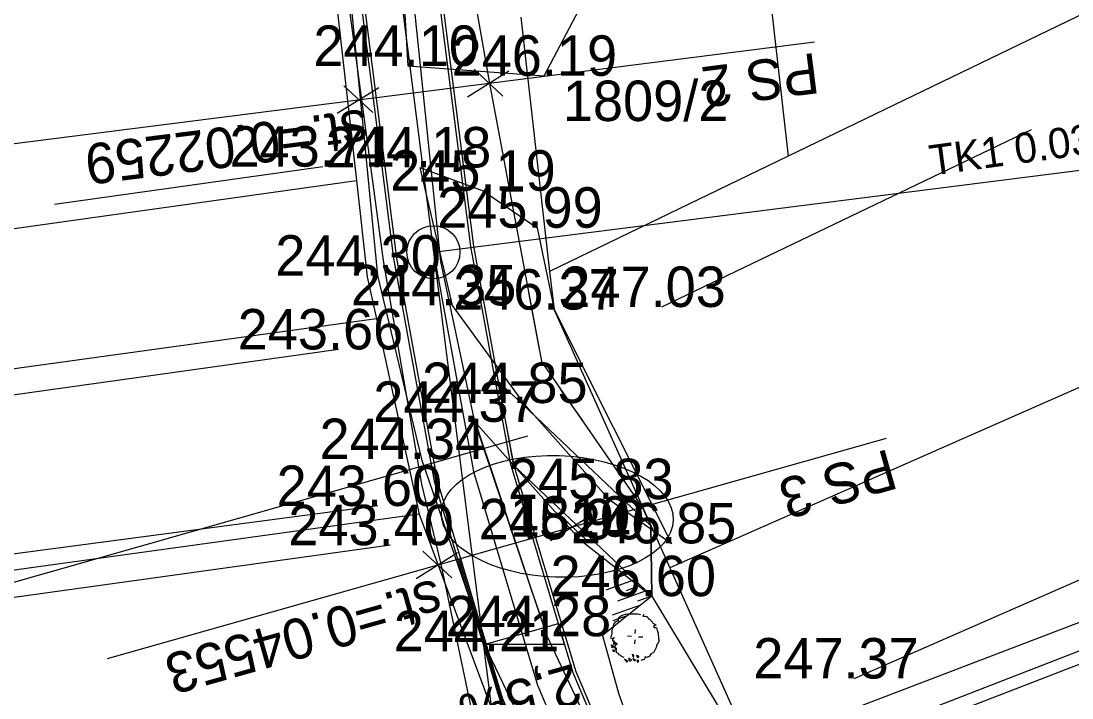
# Model space of a CAD drawing. Extents: x -601754 to -601440, y -1201912 to -1200862.
# Drawn here: x -601652.4 to -601600.5, y -1200940.1 to -1200906.7 of the extents above; entities that cross this region are included whole.
import ezdxf

# ---------------------------------------------------------------- set-up
doc = ezdxf.new("R2010")
doc.units = 0
for name, color, linetype in [('Hranice parcel', 7, 'Continuous'), ('Parcelní čísla', 7, 'Continuous'), ('u_dotčené parcely', 7, 'Continuous'), ('u_drén', 7, 'Continuous'), ('u_hrany', 7, 'Continuous'), ('u_krizky', 7, 'Continuous'), ('u_návrh', 7, 'Continuous'), ('u_oblouky', 7, 'Continuous'), ('u_osa', 7, 'Continuous'), ('u_popis', 7, 'Continuous'), ('u_popis oblouky', 7, 'Continuous'), ('u_pricne_cesta', 7, 'Continuous'), ('u_rozšíření v obloucích', 7, 'Continuous'), ('u_sklony', 7, 'Continuous'), ('u_terénní úpravy', 7, 'Continuous'), ('u_vysadba_SO_101', 7, 'Continuous'), ('u_vyska', 7, 'Continuous')]:
    doc.layers.add(name, color=color, linetype=linetype)

msp = doc.modelspace()

# ---------------------------------------------------------------- linework, layer by layer
at = {"layer": 'Hranice parcel'}
for p, q in [((-601637.83, -1200896.61), (-601635.81, -1200914.55)), ((-601615.91, -1200900.68), (-601614.48, -1200913.35)), ((-601627.69, -1200906.47), (-601626.27, -1200919.05)), ((-601614.48, -1200913.35), (-601626.27, -1200919.05)), ((-601751.585, -1200930.722), (-601635.81, -1200914.55)), ((-601634.83, -1200921.38), (-601751.585, -1200937.583)), ((-601634.83, -1200921.38), (-601632.72, -1200931.05)), ((-601632.72, -1200931.05), (-601751.585, -1200947.48)), ((-601632.72, -1200931.05), (-601626.75, -1200947.04)), ((-601620.33, -1200933.7), (-601616.34, -1200942.61))]:
    msp.add_line(p, q, dxfattribs=at)
for points in [[(-601480.72, -1200862.73), (-601552.37, -1200903.73), (-601620.33, -1200933.7)], [(-601514.155, -1200862.355), (-601515.21, -1200862.87), (-601539.23, -1200875.18), (-601559.8, -1200886.93), (-601614.48, -1200913.35)], [(-601474.14, -1200873.18), (-601548.57, -1200915.94), (-601568.93, -1200924.49), (-601616.34, -1200942.61)], [(-601472.81, -1200874.75), (-601548.9, -1200918.67), (-601615.4, -1200944.4)], [(-601611.28, -1200963.08), (-601614.07, -1200959.31), (-601621.9, -1200946.57), (-601626.39, -1200937.08), (-601630.02, -1200926.25), (-601631.65, -1200918.55), (-601633.57, -1200899.96), (-601633.33, -1200887.98), (-601632.07, -1200885.6), (-601629.11, -1200882.26)], [(-601635.81, -1200914.55), (-601635.28, -1200919.31), (-601634.83, -1200921.38)], [(-601626.27, -1200919.05), (-601626.05, -1200920.94), (-601620.33, -1200933.7)]]:
    msp.add_lwpolyline(points, dxfattribs=at)
at = {"layer": 'u_dotčené parcely'}
msp.add_ellipse((-601625.886, -1200931.156), major_axis=(-5.729, 0.182), ratio=0.524694, dxfattribs=at)
at = {"layer": 'u_drén'}
msp.add_lwpolyline([(-601630.738, -1200933.27), (-601628.676, -1200940.153), (-601624.291, -1200950.498), (-601618.798, -1200960.3), (-601612.295, -1200969.398), (-601587.744, -1201000.039)], dxfattribs=at)
at = {"layer": 'u_hrany'}
for points in [[(-601637.65, -1200892.44), (-601636.56, -1200901.01), (-601634.78, -1200919.25), (-601632.6, -1200928.32), (-601629.33, -1200937.82), (-601624.51, -1200947.91), (-601616.86, -1200961.13), (-601606.97, -1200974.25), (-601596.82, -1200985.88), (-601582.46, -1201002.22), (-601574.49, -1201012.64), (-601569.33, -1201022.81), (-601566.79, -1201038.25), (-601566.21, -1201048.21)], [(-601634.24, -1200892.15), (-601633.27, -1200908.88), (-601626.53, -1200909.37)], [(-601626.53, -1200909.37), (-601624.49, -1200905.48)], [(-601620.72, -1200920.8), (-601602.45, -1200912.02)], [(-601650.73, -1200915.71), (-601637.47, -1200913.86)], [(-601632.69, -1200913.9), (-601629.56, -1200915.05), (-601626.89, -1200916.88)], [(-601632.69, -1200913.9), (-601631.08, -1200920.72), (-601627.56, -1200925.55), (-601623.34, -1200930.3), (-601620.24, -1200932.49)], [(-601626.89, -1200916.88), (-601626.05, -1200920.93), (-601620.24, -1200932.49)], [(-601636.71, -1200922.9), (-601654.69, -1200925.42)], [(-601629.97, -1200926.48), (-601624.78, -1200932.29), (-601621.22, -1200935.1)], [(-601568.57, -1201015.08), (-601571.45, -1201010.54), (-601577.11, -1201003.42), (-601594.37, -1200984.29), (-601604.5, -1200972.6), (-601614.07, -1200959.31), (-601621.9, -1200946.57), (-601626.39, -1200937.08), (-601629.97, -1200926.48)], [(-601634.75, -1200930.64), (-601653.18, -1200933.08)], [(-601611.21, -1200939.17), (-601592.25, -1200930.86)], [(-601634.14, -1200932.58), (-601652.73, -1200935.16)], [(-601611.85, -1200942.37), (-601592.5, -1200934.86)], [(-601621.22, -1200935.1), (-601608.09, -1200956.91)], [(-601629.33, -1200937.82), (-601626.28, -1200948.41), (-601618.2, -1200962.23), (-601609.12, -1200975.86), (-601600.84, -1200990.01)]]:
    msp.add_lwpolyline(points, dxfattribs=at)
at = {"layer": 'u_krizky'}
for p, q in [((-601628.572, -1200910.369), (-601629.998, -1200909.049)), ((-601628.279, -1200909.142), (-601630.331, -1200910.422)), ((-601634.715, -1200909.96), (-601636.768, -1200911.24)), ((-601635.009, -1200911.186), (-601636.435, -1200909.867)), ((-601624.166, -1200931.081), (-601626.218, -1200932.36)), ((-601624.459, -1200932.307), (-601625.885, -1200930.987)), ((-601630.814, -1200932.962), (-601632.867, -1200934.242)), ((-601631.107, -1200934.188), (-601632.534, -1200932.869))]:
    msp.add_line(p, q, dxfattribs=at)
at = {"layer": 'u_návrh'}
for p, q in [((-601621.265, -1200931.615), (-601628.812, -1200924.471)), ((-601621.22, -1200935.1), (-601628.022, -1200928.661)), ((-601621.22, -1200935.1), (-601621.265, -1200931.615))]:
    msp.add_line(p, q, dxfattribs=at)
for points in [[(-601634.025, -1200887.577), (-601630.185, -1200917.812), (-601628.225, -1200928.505), (-601625.119, -1200938.871), (-601620.896, -1200948.834), (-601615.607, -1200958.274), (-601609.285, -1200967.119), (-601584.73, -1200997.764)], [(-601633.876, -1200887.558), (-601630.036, -1200917.789), (-601628.079, -1200928.47), (-601624.978, -1200938.82), (-601620.761, -1200948.768), (-601615.48, -1200958.194), (-601609.165, -1200967.028), (-601578.723, -1201005.021)], [(-601637.844, -1200888.062), (-601633.991, -1200918.402), (-601631.974, -1200929.408), (-601628.747, -1200940.179), (-601624.358, -1200950.531), (-601618.862, -1200960.341), (-601612.355, -1200969.444), (-601581.832, -1201007.537)], [(-601637.695, -1200888.043), (-601633.842, -1200918.379), (-601631.828, -1200929.372), (-601628.605, -1200940.128), (-601624.223, -1200950.465), (-601618.735, -1200960.26), (-601612.236, -1200969.353), (-601587.617, -1201000.078)], [(-601621.265, -1200931.615), (-601621.673, -1200930.705), (-601626.671, -1200923.479)]]:
    msp.add_lwpolyline(points, dxfattribs=at)
at = {"layer": 'u_oblouky'}
for q in [(-601592.583, -1200913.087), (-601628.449, -1200946.159)]:
    msp.add_line((-601632.013, -1200918.095), q, dxfattribs=at)
msp.add_circle((-601632.013, -1200918.095), 1.311, dxfattribs=at)
at = {"layer": 'u_osa'}
msp.add_lwpolyline([(-601635.86, -1200887.81), (-601632.013, -1200918.095), (-601630.026, -1200928.939), (-601626.862, -1200939.5), (-601622.56, -1200949.65), (-601617.171, -1200959.267), (-601610.76, -1200968.236), (-601578.672, -1201008.284), (-601575.031, -1201013.469), (-601572.075, -1201019.074), (-601569.852, -1201025.007), (-601568.398, -1201031.174), (-601566.15, -1201044.408), (-601565.576, -1201049.148), (-601565.456, -1201053.922), (-601565.793, -1201058.685), (-601566.228, -1201062.343), (-601567.198, -1201067.854), (-601568.778, -1201073.221), (-601570.948, -1201078.378), (-601573.681, -1201083.261), (-601575.226, -1201085.692), (-601578.132, -1201090.011)], dxfattribs=at)
at = {"layer": 'u_popis'}
msp.add_line((-601660.34, -1200936.567), (-601627.341, -1200927.164), dxfattribs=at)
at = {"layer": 'u_pricne_cesta'}
for points in [[(-601613.173, -1200907.704), (-601633.013, -1200910.224), (-601652.854, -1200912.744)], [(-601609.641, -1200927.3), (-601628.886, -1200932.746), (-601648.13, -1200938.191)]]:
    msp.add_lwpolyline(points, dxfattribs=at)
at = {"layer": 'u_rozšíření v obloucích'}
msp.add_lwpolyline([(-601621.265, -1200931.615), (-601621.22, -1200935.1), (-601628.022, -1200928.661), (-601628.812, -1200924.471)], close=True, dxfattribs=at)
at = {"layer": 'u_sklony'}
for p, q in [((-601627.308, -1200920.08), (-601626.763, -1200922.985)), ((-601625.751, -1200924.863), (-601624.653, -1200926.396)), ((-601622.39, -1200933.992), (-601623.096, -1200934.246)), ((-601622.076, -1200934.289), (-601623.488, -1200934.798)), ((-601621.501, -1200934.834), (-601622.912, -1200935.343)), ((-601621.776, -1200934.573), (-601622.482, -1200934.828)), ((-601621.77, -1200935.539), (-601623.181, -1200936.047)), ((-601621.22, -1200935.1), (-601621.926, -1200935.354)), ((-601622.436, -1200936.07), (-601623.141, -1200936.324)), ((-601629.28, -1200938.398), (-601628.822, -1200939.928))]:
    msp.add_line(p, q, dxfattribs=at)
msp.add_lwpolyline([(-601625.84, -1200936.466), (-601629.4, -1200937.474), (-601625.54, -1200937.466)], close=True, dxfattribs=at)
at = {"layer": 'u_terénní úpravy'}
msp.add_line((-601621.22, -1200935.1), (-601623.651, -1200937.04), dxfattribs=at)
for points in [[(-601633.16, -1200887.467), (-601629.246, -1200909.745), (-601626.671, -1200923.479)], [(-601638.582, -1200888.156), (-601634.493, -1200918.503), (-601632.607, -1200929.56), (-601631.638, -1200933.524), (-601630.127, -1200940.76), (-601625.442, -1200954.325), (-601625.442, -1200954.325), (-601620.62, -1200961.457), (-601614.291, -1200970.175), (-601602.86, -1200984.783)], [(-601623.651, -1200937.04), (-601622.862, -1200939.893), (-601618.936, -1200950.908), (-601615.274, -1200957.893), (-601609.075, -1200966.053), (-601604.07, -1200972.745), (-601597.484, -1200980.476), (-601592.22, -1200988.176), (-601585.958, -1200994.904), (-601578.723, -1201005.021), (-601574.41, -1201008.093), (-601573.524, -1201008.969), (-601571.743, -1201011.837), (-601569.512, -1201016.171), (-601566.023, -1201016.188)]]:
    msp.add_lwpolyline(points, dxfattribs=at)
at = {"layer": 'u_vysadba_SO_101'}
for points in [[(-601623.037, -1200936.403), (-601623.036, -1200936.374), (-601622.976, -1200936.348), (-601622.946, -1200936.335), (-601622.916, -1200936.321), (-601622.887, -1200936.323), (-601622.858, -1200936.325), (-601622.871, -1200936.295), (-601622.884, -1200936.265), (-601622.867, -1200936.222), (-601622.85, -1200936.179), (-601622.818, -1200936.136), (-601622.788, -1200936.109), (-601622.757, -1200936.081), (-601622.712, -1200936.054), (-601622.668, -1200936.056), (-601622.637, -1200936.029), (-601622.562, -1200936.003), (-601622.503, -1200935.992), (-601622.459, -1200935.98), (-601622.4, -1200935.983), (-601622.356, -1200935.97), (-601622.312, -1200935.973), (-601622.239, -1200935.977), (-601622.165, -1200935.966), (-601622.092, -1200935.97), (-601622.004, -1200935.974), (-601621.917, -1200935.979), (-601621.844, -1200935.983), (-601621.801, -1200936), (-601621.772, -1200936.016)], [(-601621.626, -1200936.009), (-601621.642, -1200936.037), (-601621.643, -1200936.067), (-601621.659, -1200936.095), (-601621.615, -1200936.083), (-601621.586, -1200936.084), (-601621.556, -1200936.086), (-601621.513, -1200936.103), (-601621.47, -1200936.105), (-601621.427, -1200936.137), (-601621.4, -1200936.167), (-601621.373, -1200936.213), (-601621.331, -1200936.244), (-601621.274, -1200936.291), (-601621.233, -1200936.337), (-601621.205, -1200936.368), (-601621.165, -1200936.429), (-601621.108, -1200936.461), (-601621.065, -1200936.492), (-601621.022, -1200936.509), (-601621.024, -1200936.539)], [(-601623.037, -1200936.403), (-601623.038, -1200936.418), (-601623.084, -1200936.459), (-601623.115, -1200936.487), (-601623.117, -1200936.53), (-601623.12, -1200936.574), (-601623.123, -1200936.633), (-601623.14, -1200936.676), (-601623.156, -1200936.704), (-601623.172, -1200936.733), (-601623.19, -1200936.79), (-601623.191, -1200936.819), (-601623.194, -1200936.878), (-601623.197, -1200936.922), (-601623.198, -1200936.951), (-601623.217, -1200937.023), (-601623.234, -1200937.066), (-601623.236, -1200937.11), (-601623.252, -1200937.138), (-601623.239, -1200937.168), (-601623.196, -1200937.185), (-601623.107, -1200937.161), (-601623.077, -1200937.148), (-601623.109, -1200937.204), (-601623.14, -1200937.232), (-601623.156, -1200937.261), (-601623.158, -1200937.304), (-601623.129, -1200937.306), (-601623.085, -1200937.308), (-601623.072, -1200937.338), (-601623.089, -1200937.381), (-601623.105, -1200937.41), (-601623.108, -1200937.453), (-601623.11, -1200937.497)], [(-601621.024, -1200936.539), (-601621.068, -1200936.551), (-601621.113, -1200936.563), (-601621.129, -1200936.592), (-601621.116, -1200936.622), (-601621.089, -1200936.667), (-601621.059, -1200936.654), (-601621.015, -1200936.642), (-601620.987, -1200936.672), (-601620.974, -1200936.702), (-601620.976, -1200936.731), (-601620.949, -1200936.791), (-601620.937, -1200936.836), (-601620.925, -1200936.881), (-601620.898, -1200936.926), (-601620.9, -1200936.955), (-601620.902, -1200936.999), (-601620.903, -1200937.028), (-601620.891, -1200937.073), (-601620.88, -1200937.132), (-601620.883, -1200937.19), (-601620.871, -1200937.249), (-601620.873, -1200937.279), (-601620.874, -1200937.308), (-601620.877, -1200937.352), (-601620.907, -1200937.379), (-601620.909, -1200937.409), (-601620.926, -1200937.452), (-601620.942, -1200937.48), (-601620.988, -1200937.522), (-601620.991, -1200937.58), (-601621.009, -1200937.638), (-601621.027, -1200937.71), (-601621.074, -1200937.766), (-601621.107, -1200937.837), (-601621.139, -1200937.894), (-601621.199, -1200937.92), (-601621.23, -1200937.948), (-601621.276, -1200937.989), (-601621.308, -1200938.032), (-601621.325, -1200938.075), (-601621.385, -1200938.101), (-601621.429, -1200938.113), (-601621.459, -1200938.126), (-601621.502, -1200938.109), (-601621.545, -1200938.092), (-601621.562, -1200938.135), (-601621.58, -1200938.193), (-601621.597, -1200938.236), (-601621.641, -1200938.248), (-601621.685, -1200938.246)], [(-601622.222, -1200937.096), (-601622.426, -1200937.085)], [(-601622.038, -1200936.944), (-601622.027, -1200936.74)], [(-601621.871, -1200937.114), (-601621.666, -1200937.111)], [(-601623.241, -1200937.49), (-601623.228, -1200937.52), (-601623.216, -1200937.565), (-601623.203, -1200937.595), (-601623.204, -1200937.624), (-601623.176, -1200937.64), (-601623.145, -1200937.613), (-601623.099, -1200937.571), (-601623.128, -1200937.57), (-601623.171, -1200937.538), (-601623.214, -1200937.521)], [(-601623.084, -1200937.557), (-601623.042, -1200937.603), (-601623.001, -1200937.649), (-601622.959, -1200937.681)], [(-601622.959, -1200937.681), (-601622.988, -1200937.679), (-601623.017, -1200937.678), (-601623.046, -1200937.676), (-601623.059, -1200937.646), (-601623.058, -1200937.617), (-601623.071, -1200937.587)], [(-601623.059, -1200937.368), (-601623.061, -1200937.412), (-601623.048, -1200937.442), (-601623.036, -1200937.487), (-601623.023, -1200937.517), (-601622.994, -1200937.518), (-601622.978, -1200937.49), (-601622.918, -1200937.463), (-601622.961, -1200937.447), (-601622.989, -1200937.43), (-601623.046, -1200937.398)], [(-601622.054, -1200937.251), (-601622.065, -1200937.455)], [(-601623.151, -1200937.729), (-601623.141, -1200937.818), (-601623.098, -1200937.82), (-601623.068, -1200937.822), (-601623.024, -1200937.809), (-601623.082, -1200937.792), (-601623.125, -1200937.789), (-601623.138, -1200937.759)], [(-601622.587, -1200938.14), (-601622.63, -1200938.123), (-601622.659, -1200938.107), (-601622.688, -1200938.105), (-601622.715, -1200938.06), (-601622.743, -1200938.044), (-601622.786, -1200938.012), (-601622.829, -1200937.995), (-601622.87, -1200937.949), (-601622.898, -1200937.918), (-601622.969, -1200937.885), (-601622.967, -1200937.842), (-601622.965, -1200937.798), (-601622.978, -1200937.768), (-601623.006, -1200937.752), (-601622.975, -1200937.709), (-601622.945, -1200937.711)], [(-601622.354, -1200938.152), (-601622.358, -1200938.225), (-601622.345, -1200938.27), (-601622.318, -1200938.301), (-601622.259, -1200938.289), (-601622.228, -1200938.261), (-601622.241, -1200938.231), (-601622.284, -1200938.214), (-601622.327, -1200938.198)], [(-601622.183, -1200937.971), (-601622.172, -1200938.045), (-601622.146, -1200938.09), (-601622.101, -1200938.078), (-601622.099, -1200938.049), (-601622.098, -1200938.019), (-601622.141, -1200938.002), (-601622.169, -1200937.986)], [(-601622.149, -1200938.148), (-601622.065, -1200938.226), (-601622.036, -1200938.242), (-601622.023, -1200938.272), (-601622.054, -1200938.3), (-601622.083, -1200938.298), (-601622.096, -1200938.268), (-601622.123, -1200938.223), (-601622.151, -1200938.192)], [(-601621.98, -1200938.011), (-601621.954, -1200938.071), (-601621.942, -1200938.115), (-601621.914, -1200938.146), (-601621.884, -1200938.133), (-601621.853, -1200938.091), (-601621.851, -1200938.062), (-601621.895, -1200938.059), (-601621.923, -1200938.043), (-601621.952, -1200938.027), (-601621.981, -1200938.025)], [(-601622.576, -1200938.199), (-601622.48, -1200938.321), (-601622.453, -1200938.367), (-601622.421, -1200938.324), (-601622.42, -1200938.295), (-601622.448, -1200938.279), (-601622.491, -1200938.262), (-601622.52, -1200938.246), (-601622.548, -1200938.23)], [(-601621.95, -1200938.261), (-601621.939, -1200938.335), (-601621.926, -1200938.365), (-601621.896, -1200938.352), (-601621.864, -1200938.31), (-601621.892, -1200938.279), (-601621.92, -1200938.263), (-601621.95, -1200938.261)], [(-601621.685, -1200938.246), (-601621.73, -1200938.258), (-601621.761, -1200938.286)]]:
    msp.add_lwpolyline(points, dxfattribs=at)

# ---------------------------------------------------------------- texts
at = {"layer": 'Parcelní čísla'}
for s, p in [('1809/2', (-601625.614, -1200911.606)), ('1810', (-601628.24, -1200932.156))]:
    msp.add_text(s, height=2, dxfattribs=at).set_placement(p)
at = {"layer": 'u_popis oblouky'}
msp.add_text('TK1 0.03053', height=1.5, rotation=7.7303, dxfattribs=at).set_placement((-601607.392, -1200914.306))
at = {"layer": 'u_pricne_cesta'}
for s, rotation, p in [('PS 2', 187.2385, (-601613.106, -1200908.227)), ('st.=0.02259', 187.2385, (-601635.383, -1200911.013)), ('PS 3', 195.799, (-601609.498, -1200927.808)), ('st.=0.04553', 195.799, (-601631.898, -1200934.231))]:
    msp.add_text(s, height=2, rotation=rotation, dxfattribs=at).set_placement(p)
at = {"layer": 'u_sklony'}
msp.add_text('2,5%', height=2, rotation=195.799, dxfattribs=at).set_placement((-601625.061, -1200938.417))
at = {"layer": 'u_vyska'}
for s, p in [('244.10', (-601637.942, -1200908.88)), ('246.19', (-601631.113, -1200909.37)), ('243.71', (-601642.09, -1200913.86)), ('244.18', (-601637.331, -1200913.9)), ('245.19', (-601634.149, -1200915.05)), ('245.99', (-601631.825, -1200916.88)), ('244.30', (-601639.823, -1200919.25)), ('244.35', (-601636.092, -1200920.72)), ('246.37', (-601631.034, -1200920.93)), ('247.03', (-601625.74, -1200920.8)), ('243.66', (-601641.684, -1200922.9)), ('244.85', (-601632.572, -1200925.55)), ('244.37', (-601634.986, -1200926.48)), ('244.34', (-601637.64, -1200928.32)), ('245.83', (-601628.324, -1200930.3)), ('243.60', (-601639.76, -1200930.64)), ('245.90', (-601629.77, -1200932.29)), ('243.40', (-601639.183, -1200932.58)), ('246.85', (-601625.219, -1200932.49)), ('246.60', (-601626.224, -1200935.1)), ('244.28', (-601631.402, -1200937.08)), ('244.21', (-601633.973, -1200937.82)), ('247.37', (-601616.203, -1200939.17))]:
    msp.add_text(s, height=2, dxfattribs=at).set_placement(p)

doc.saveas('drawing.dxf')
